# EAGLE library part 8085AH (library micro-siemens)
MICROPROCESSOR/PERIPHERAL DEVICE
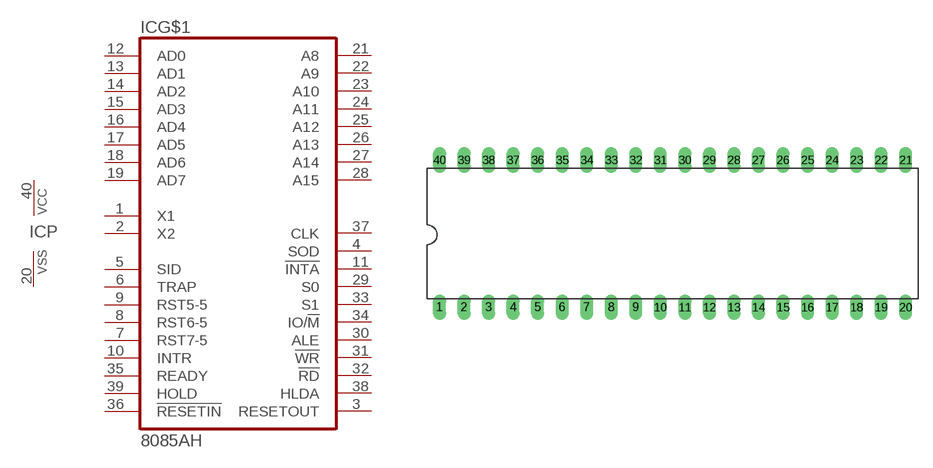
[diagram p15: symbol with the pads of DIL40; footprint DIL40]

Designator prefix IC; gates G$1=8085AH P=VCCVSS

## 8085AH (OC_FARNELL: unknown; OC_NEWARK: unknown)  [DIL40]
1  G$1:X1  in
2  G$1:X2  in
3  G$1:RESETOUT  out
4  G$1:SOD  out
5  G$1:SID  in
6  G$1:TRAP  in
7  G$1:RST7-5  in
8  G$1:RST6-5  in
9  G$1:RST5-5  in
10  G$1:INTR  in
11  G$1:!INTA  out
12  G$1:AD0
13  G$1:AD1
14  G$1:AD2
15  G$1:AD3
16  G$1:AD4
17  G$1:AD5
18  G$1:AD6
19  G$1:AD7
20  P:VSS  pwr
21  G$1:A8  out
22  G$1:A9  out
23  G$1:A10  out
24  G$1:A11  out
25  G$1:A12  out
26  G$1:A13  out
27  G$1:A14  out
28  G$1:A15  out
29  G$1:S0  out
30  G$1:ALE  out
31  G$1:!WR  out
32  G$1:!RD  out
33  G$1:S1  out
34  G$1:IO/!M  out
35  G$1:READY  in
36  G$1:!RESETIN  in
37  G$1:CLK  out
38  G$1:HLDA  out
39  G$1:HOLD  in
40  P:VCC  pwr

## Footprint DIL40 (pad centres in mm)
Dual In Line Package
drill 0.813 long: 1 -24.13,-7.62; 2 -21.59,-7.62; 3 -19.05,-7.62; 4 -16.51,-7.62; 5 -13.97,-7.62; 6 -11.43,-7.62; 7 -8.89,-7.62; 8 -6.35,-7.62; 9 -3.81,-7.62; 10 -1.27,-7.62; 11 1.27,-7.62; 12 3.81,-7.62; 13 6.35,-7.62; 14 8.89,-7.62; 15 11.43,-7.62; 16 13.97,-7.62; 17 16.51,-7.62; 18 19.05,-7.62; 19 21.59,-7.62; 20 24.13,-7.62; 21 24.13,7.62; 22 21.59,7.62; 23 19.05,7.62; 24 16.51,7.62; 25 13.97,7.62; 26 11.43,7.62; 27 8.89,7.62; 28 6.35,7.62; 29 3.81,7.62; 30 1.27,7.62; 31 -1.27,7.62; 32 -3.81,7.62; 33 -6.35,7.62; 34 -8.89,7.62; 35 -11.43,7.62; 36 -13.97,7.62; 37 -16.51,7.62; 38 -19.05,7.62; 39 -21.59,7.62; 40 -24.13,7.62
